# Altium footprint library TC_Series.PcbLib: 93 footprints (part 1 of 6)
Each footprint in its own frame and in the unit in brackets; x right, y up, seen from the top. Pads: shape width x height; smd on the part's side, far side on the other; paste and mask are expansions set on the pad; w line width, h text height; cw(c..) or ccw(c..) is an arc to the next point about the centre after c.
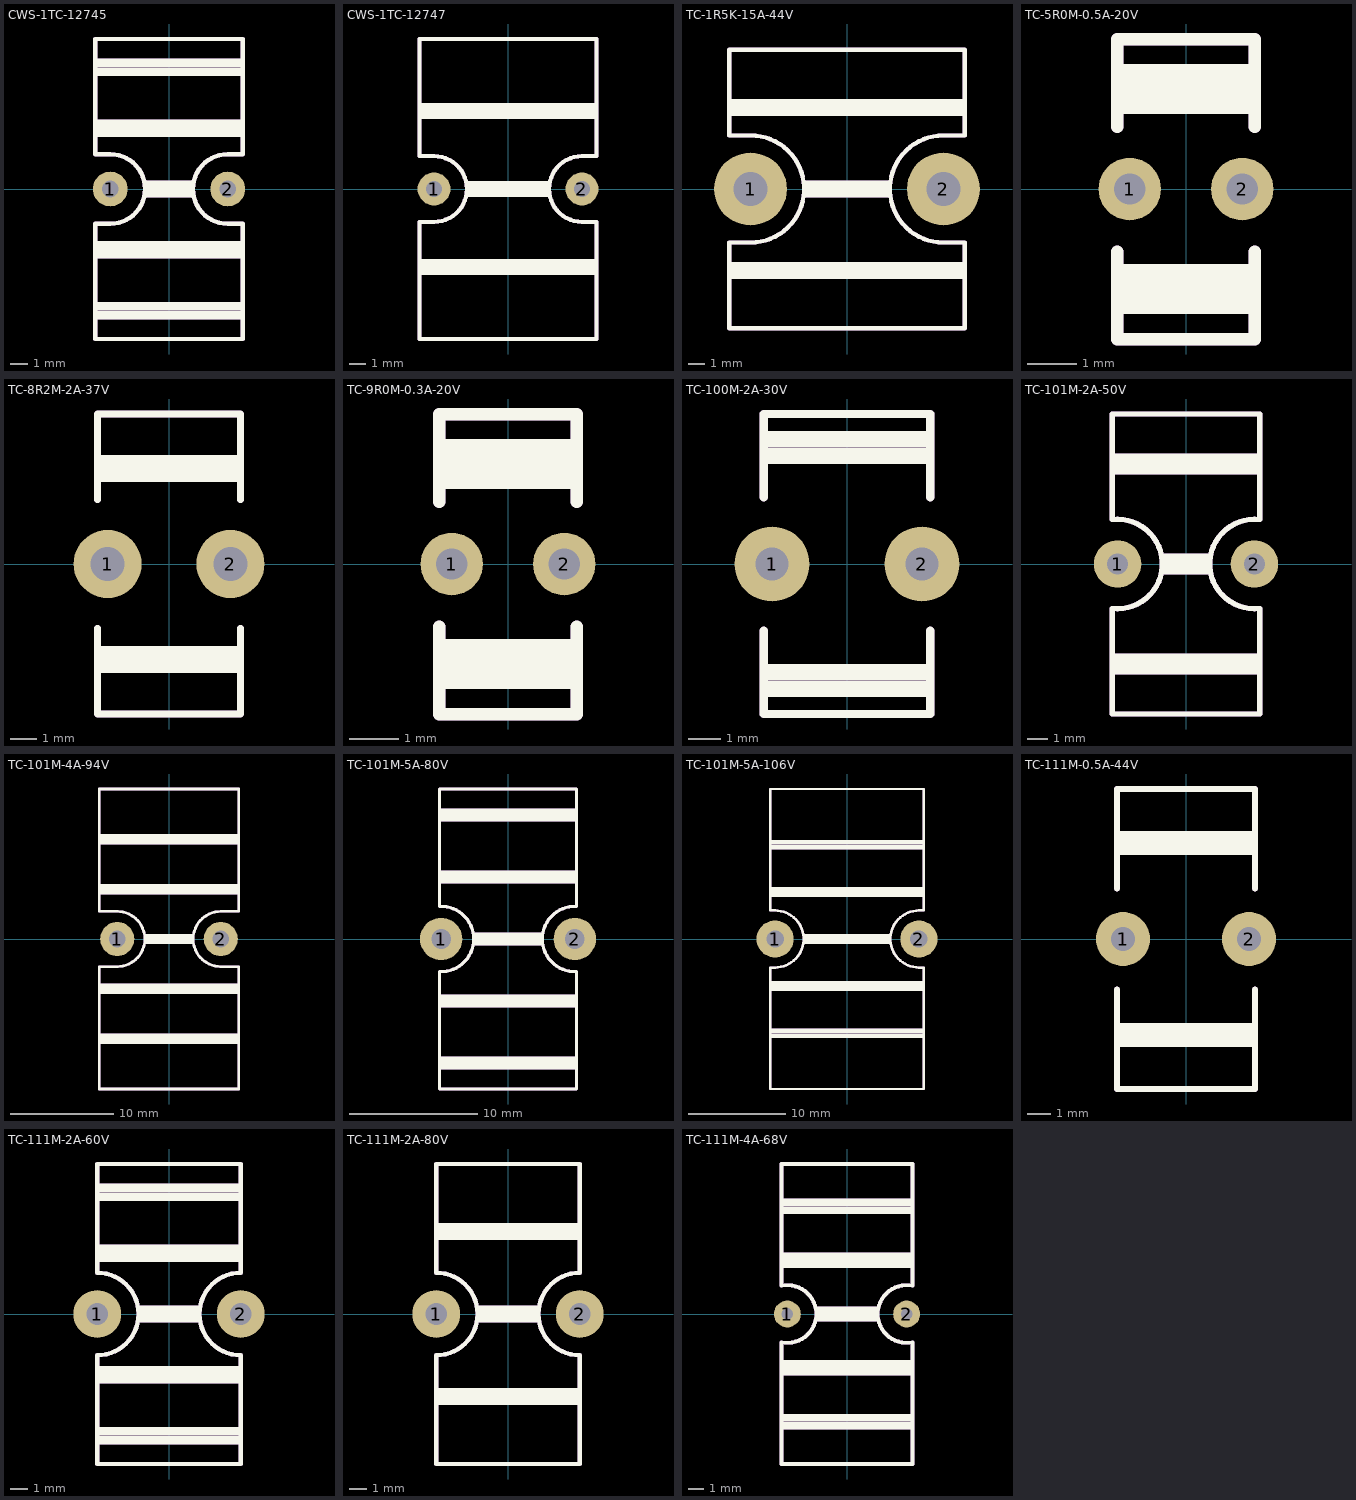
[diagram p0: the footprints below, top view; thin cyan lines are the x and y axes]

## CWS-1TC-12745 [mil]
pads (2):
  round 80 hole 38: 1(-135,0) 2(135,0)
Top Overlay:
  lines w10: -170,-345 -170,-80 -135,-80 ccw(c-135,0) -135,80 -170,80 -170,345 170,345 170,80 135,80 ccw(c135,0) 135,-80 170,-80 170,-345 -170,-345
  lines w19.68: -165,-290 165,-290 ; -165,-270 165,-270 ; -165,-150 165,-150 ; -165,-130 165,-130 ; -165,130 165,130 ; -165,150 165,150 ; -165,270 165,270 ; -165,290 165,290 ; -50,-10 50,-10 ; -50,10 50,10
Mechanical 29:
  lines w10: -170,-345 -170,-80 -135,-80 ccw(c-135,0) -135,80 -170,80 -170,345 170,345 170,80 135,80 ccw(c135,0) 135,-80 170,-80 170,-345 -170,-345
  lines w19.68: -165,-290 165,-290 ; -165,-270 165,-270 ; -165,-150 165,-150 ; -165,-130 165,-130 ; -165,130 165,130 ; -165,150 165,150 ; -165,270 165,270 ; -165,290 165,290 ; -50,-10 50,-10 ; -50,10 50,10
  text "'.Designator'" at -1750,-64.85 h400

## CWS-1TC-12747 [mil]
pads (2):
  round 80 hole 38: 1(-180,0) 2(180,0)
Top Overlay:
  lines w10: 215,-83.71 215,-365 -215,-365 -215,-80 -180,-80 ccw(c-180,0) -180,80 -215,80 -215,365 215,365 215,83.71 ; 215,-80 180,-80 cw(c180,0) 180,80 215,80
  lines w19.68: -210,-200 210,-200 ; -210,-180 210,-180 ; -210,180 210,180 ; -210,200 210,200 ; -95,-10 95,-10 ; -95,10 95,10
Mechanical 29:
  lines w10: 215,-83.71 215,-365 -215,-365 -215,-80 -180,-80 ccw(c-180,0) -180,80 -215,80 -215,365 215,365 215,83.71 ; 215,-80 180,-80 cw(c180,0) 180,80 215,80
  lines w19.68: -210,-200 210,-200 ; -210,-180 210,-180 ; -210,180 210,180 ; -210,200 210,200 ; -95,-10 95,-10 ; -95,10 95,10
  text "'.Designator'" at -1750,-64.85 h400

## PCBComponent_1 [mil]

## TC-1R5K-15A-44V [mil]
pads (2):
  round 170 hole 80: 1(-225,0) 2(225,0)
Top Overlay:
  lines w10: -275,-325 275,-325 275,-125 225,-125 cw(c225,0) 225,125 275,125 275,325 -275,325 -275,125 -225,125 cw(c-225,0) -225,-125 -275,-125 -275,-325
  lines w19.68: -270,-200 270,-200 ; -270,-180 270,-180 ; -270,180 270,180 ; -270,200 270,200 ; -95,-10 95,-10 ; -95,10 95,10
Mechanical 29:
  lines w10: -275,-325 275,-325 275,-125 225,-125 cw(c225,0) 225,125 275,125 275,325 -275,325 -275,125 -225,125 cw(c-225,0) -225,-125 -275,-125 -275,-325
  lines w19.68: -270,-200 270,-200 ; -270,-180 270,-180 ; -270,180 270,180 ; -270,200 270,200 ; -95,-10 95,-10 ; -95,10 95,10
  text "'.Designator'" at -1750,-64.85 h400

## TC-5R0M-0.5A-20V [mil]
pads (2):
  round 50 hole 25: 1(-45,0) 2(45,0)
Top Overlay:
  lines w10: -55,-50 -55,-120 55,-120 55,-50 ; -55,50 -55,120 55,120 55,50
  lines w19.68: -50,-90 50,-90 ; -50,-70 50,-70 ; -50,70 50,70 ; -50,90 50,90
Mechanical 29:
  lines w10: -55,-50 -55,-120 55,-120 55,-50 ; -55,50 -55,120 55,120 55,50
  lines w19.68: -50,-90 50,-90 ; -50,-70 50,-70 ; -50,70 50,70 ; -50,90 50,90
  text "'.Designator'" at -750,-12.45 h200

## TC-8R2M-2A-37V [mil]
pads (2):
  round 100 hole 50: 1(-90,0) 2(90,0)
Top Overlay:
  lines w10: -105,-94.35 -105,-220 105,-220 105,-94.35 ; -105,94.35 -105,220 105,220 105,94.35
  lines w19.68: -100,-150 100,-150 ; -100,-130 100,-130 ; -100,130 100,130 ; -100,150 100,150
Mechanical 29:
  lines w10: -105,-94.35 -105,-220 105,-220 105,-94.35 ; -105,94.35 -105,220 105,220 105,94.35
  lines w19.68: -100,-150 100,-150 ; -100,-130 100,-130 ; -100,130 100,130 ; -100,150 100,150
  text "'.Designator'" at -850,-12.45 h200

## TC-9R0M-0.3A-20V [mil]
pads (2):
  round 50 hole 25: 1(-45,0) 2(45,0)
Top Overlay:
  lines w10: -55,-50 -55,-120 55,-120 55,-50 ; -55,50 -55,120 55,120 55,50
  lines w19.68: -50,-90 50,-90 ; -50,-70 50,-70 ; -50,70 50,70 ; -50,90 50,90
Mechanical 29:
  lines w10: -55,-50 -55,-120 55,-120 55,-50 ; -55,50 -55,120 55,120 55,50
  lines w19.68: -50,-90 50,-90 ; -50,-70 50,-70 ; -50,70 50,70 ; -50,90 50,90
  text "'.Designator'" at -800,-62.45 h200

## TC-100M-2A-30V [mil]
pads (2):
  round 90 hole 40: 1(-90,0) 2(90,0)
Top Overlay:
  lines w10: -100,-80 -100,-180 100,-180 100,-80 ; -100,80 -100,180 100,180 100,80
  lines w19.68: -95,-150 95,-150 ; -95,-130 95,-130 ; -95,130 95,130 ; -95,150 95,150
Mechanical 29:
  lines w10: -100,-80 -100,-180 100,-180 100,-80 ; -100,80 -100,180 100,180 100,80
  lines w19.68: -95,-150 95,-150 ; -95,-130 95,-130 ; -95,130 95,130 ; -95,150 95,150
  text "'.Designator'" at -800,-62.45 h200

## TC-101M-2A-50V [mil]
pads (2):
  round 90 hole 40: 1(-130,0) 2(130,0)
Top Overlay:
  lines w10: -140,84.42 -140,285 140,285 140,84.83 ; -139.93,84.42 cw(c-130,0) -140,-84.41 -140,-285 140,-285 140,-84.83 ; 139.95,-84.42 cw(c130,0) 139.95,84.42
  lines w19.68: -135,-200 135,-200 ; -135,-180 135,-180 ; -135,180 135,180 ; -135,200 135,200 ; -40,-10 40,-10 ; -40,10 40,10
Mechanical 29:
  lines w10: -140,84.42 -140,285 140,285 140,84.83 ; -139.93,84.42 cw(c-130,0) -140,-84.41 -140,-285 140,-285 140,-84.83 ; 139.95,-84.42 cw(c130,0) 139.95,84.42
  lines w19.68: -135,-200 135,-200 ; -135,-180 135,-180 ; -135,180 135,180 ; -135,200 135,200 ; -40,-10 40,-10 ; -40,10 40,10
  text "'.Designator'" at -1750,-64.85 h400

## TC-101M-4A-94V [mil]
pads (2):
  round 130 hole 63: 1(-197,0) 2(197,0)
Top Overlay:
  lines w10: -197,-105 ccw(c-197,0) -197,105 ; -195,-105 -265.5,-105 -265.5,-571 265.5,-571 265.5,-105 195,-105 ; -195,105 -265.5,105 -265.5,571 265.5,571 265.5,105 197,105 ccw(c197,0) 197,-105
  lines w19.68: -260,-390 260,-390 ; -260,-370 260,-370 ; -260,-200 260,-200 ; -260,-180 260,-180 ; -260,180 260,180 ; -260,200 260,200 ; -260,370 260,370 ; -260,390 260,390 ; -87,-10 88,-10 ; -87,10 88,10
Mechanical 29:
  lines w10: -197,-105 ccw(c-197,0) -197,105 ; -195,-105 -265.5,-105 -265.5,-571 265.5,-571 265.5,-105 195,-105 ; -195,105 -265.5,105 -265.5,571 265.5,571 265.5,105 197,105 ccw(c197,0) 197,-105
  lines w19.68: -260,-390 260,-390 ; -260,-370 260,-370 ; -260,-200 260,-200 ; -260,-180 260,-180 ; -260,180 260,180 ; -260,200 260,200 ; -260,370 260,370 ; -260,390 260,390 ; -87,-10 88,-10 ; -87,10 88,10
  text "'.Designator'" at -1750,-64.85 h400

## TC-101M-5A-80V [mil]
pads (2):
  round 130 hole 60: 1(-205,0) 2(205,0)
Top Overlay:
  lines w10: -210,-100 -210,-460 210,-460 210,-100 ; -209.99,-99.88 ccw(c-205,0) -209.99,99.88 ; -210,100 -210,460 210,460 210,100 ; 209.99,-99.88 cw(c205,0) 209.99,99.88
  lines w19.68: -205,-390 205,-390 ; -205,-370 205,-370 ; -205,-200 205,-200 ; -205,-180 205,-180 ; -205,180 205,180 ; -205,200 205,200 ; -205,370 205,370 ; -205,390 205,390 ; -100,-10 100,-10 ; -100,10 100,10
Mechanical 29:
  lines w10: -210,-100 -210,-460 210,-460 210,-100 ; -209.99,-99.88 ccw(c-205,0) -209.99,99.88 ; -210,100 -210,460 210,460 210,100 ; 209.99,-99.88 cw(c205,0) 209.99,99.88
  lines w19.68: -205,-390 205,-390 ; -205,-370 205,-370 ; -205,-200 205,-200 ; -205,-180 205,-180 ; -205,180 205,180 ; -205,200 205,200 ; -205,370 205,370 ; -205,390 205,390 ; -100,-10 100,-10 ; -100,10 100,10
  text "'.Designator'" at -1750,-64.85 h400

## TC-101M-5A-106V [mil]
pads (2):
  round 150 hole 70: 1(-290,0) 2(290,0)
Top Overlay:
  lines w10: -310,-605 -310,-115 -290,-115 ccw(c-290,0) -290,115 -310,115 -310,605 310,605 310,115 290,115 ccw(c290,0) 290,-115 310,-115 310,-605 -310,-605
  lines w19.68: -305,-390 305,-390 ; -305,-370 305,-370 ; -305,-200 305,-200 ; -305,-180 305,-180 ; -305,180 305,180 ; -305,200 305,200 ; -305,370 305,370 ; -305,390 305,390 ; -170,-10 170,-10 ; -170,10 170,10
Mechanical 29:
  lines w10: -310,-605 -310,-115 -290,-115 ccw(c-290,0) -290,115 -310,115 -310,605 310,605 310,115 290,115 ccw(c290,0) 290,-115 310,-115 310,-605 -310,-605
  lines w19.68: -305,-390 305,-390 ; -305,-370 305,-370 ; -305,-200 305,-200 ; -305,-180 305,-180 ; -305,180 305,180 ; -305,200 305,200 ; -305,370 305,370 ; -305,390 305,390 ; -170,-10 170,-10 ; -170,10 170,10
  text "'.Designator'" at -1750,-64.85 h400

## TC-111M-0.5A-44V [mil]
pads (2):
  round 90 hole 40: 1(-105,0) 2(105,0)
Top Overlay:
  lines w10: -115,-84.42 -115,-250 115,-250 115,-84.42 ; -115,84.42 -115,250 115,250 115,84.42
  lines w19.68: -110,-170 110,-170 ; -110,-150 110,-150 ; -110,150 110,150 ; -110,170 110,170
Mechanical 29:
  lines w10: -115,-84.42 -115,-250 115,-250 115,-84.42 ; -115,84.42 -115,250 115,250 115,84.42
  lines w19.68: -110,-170 110,-170 ; -110,-150 110,-150 ; -110,150 110,150 ; -110,170 110,170
  text "'.Designator'" at -765,-42.45 h200

## TC-111M-2A-60V [mil]
pads (2):
  round 110 hole 50: 1(-165,0) 2(165,0)
Top Overlay:
  lines w10: -165,-345 165,-345 165,-95 cw(c165,0) 165,95 165,345 -165,345 -165,95 cw(c-165,0) -165,-95 -165,-345
  lines w19.68: -160,-290 160,-290 ; -160,-270 160,-270 ; -160,-150 160,-150 ; -160,-130 160,-130 ; -160,130 160,130 ; -160,150 160,150 ; -160,270 160,270 ; -160,290 160,290 ; -65,-10 65,-10 ; -65,10 65,10
Mechanical 29:
  lines w10: -165,-345 165,-345 165,-95 cw(c165,0) 165,95 165,345 -165,345 -165,95 cw(c-165,0) -165,-95 -165,-345
  lines w19.68: -160,-290 160,-290 ; -160,-270 160,-270 ; -160,-150 160,-150 ; -160,-130 160,-130 ; -160,130 160,130 ; -160,150 160,150 ; -160,270 160,270 ; -160,290 160,290 ; -65,-10 65,-10 ; -65,10 65,10
  text "'.Designator'" at -1750,-64.85 h400

## TC-111M-2A-80V [mil]
pads (2):
  round 110 hole 50: 1(-165,0) 2(165,0)
Top Overlay:
  lines w10: -165,-345 165,-345 ; -165,-344.8 -165,-95 ccw(c-165,0) -165,95 -165,344.8 ; -165,345 165,345 ; 165,-344.8 165,-95 cw(c165,0) 165,95 165,344.8
  lines w19.68: -160,-200 160,-200 ; -160,-180 160,-180 ; -160,180 160,180 ; -160,200 160,200 ; -65,-10 65,-10 ; -65,10 65,10
Mechanical 29:
  lines w10: -165,-345 165,-345 ; -165,-344.8 -165,-95 ccw(c-165,0) -165,95 -165,344.8 ; -165,345 165,345 ; 165,-344.8 165,-95 cw(c165,0) 165,95 165,344.8
  lines w19.68: -160,-200 160,-200 ; -160,-180 160,-180 ; -160,180 160,180 ; -160,200 160,200 ; -65,-10 65,-10 ; -65,10 65,10
  text "'.Designator'" at -1750,-64.85 h400

## TC-111M-4A-68V [mil]
pads (2):
  round 70 hole 30: 1(-155,0) 2(155,0)
Top Overlay:
  lines w10: -170,-73.72 -170,-390 170,-390 170,-73.72 ; -170,73.72 -170,388.72 ; -170,390 170,390 ; -169.95,-73.49 ccw(c-155,0) -169.95,73.49 ; 169.95,-73.49 cw(c155,0) 169.95,73.49 ; 170,73.72 170,388.72
  lines w19.68: -165,-290 165,-290 ; -165,-270 165,-270 ; -165,-150 165,-150 ; -165,-130 165,-130 ; -165,130 165,130 ; -165,150 165,150 ; -165,270 165,270 ; -165,290 165,290 ; -75,-10 75,-10 ; -75,10 75,10
Mechanical 29:
  lines w10: -170,-73.72 -170,-390 170,-390 170,-73.72 ; -170,73.72 -170,388.72 ; -170,390 170,390 ; -169.95,-73.49 ccw(c-155,0) -169.95,73.49 ; 169.95,-73.49 cw(c155,0) 169.95,73.49 ; 170,73.72 170,388.72
  lines w19.68: -165,-290 165,-290 ; -165,-270 165,-270 ; -165,-150 165,-150 ; -165,-130 165,-130 ; -165,130 165,130 ; -165,150 165,150 ; -165,270 165,270 ; -165,290 165,290 ; -75,-10 75,-10 ; -75,10 75,10
  text "'.Designator'" at -1750,-64.85 h400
